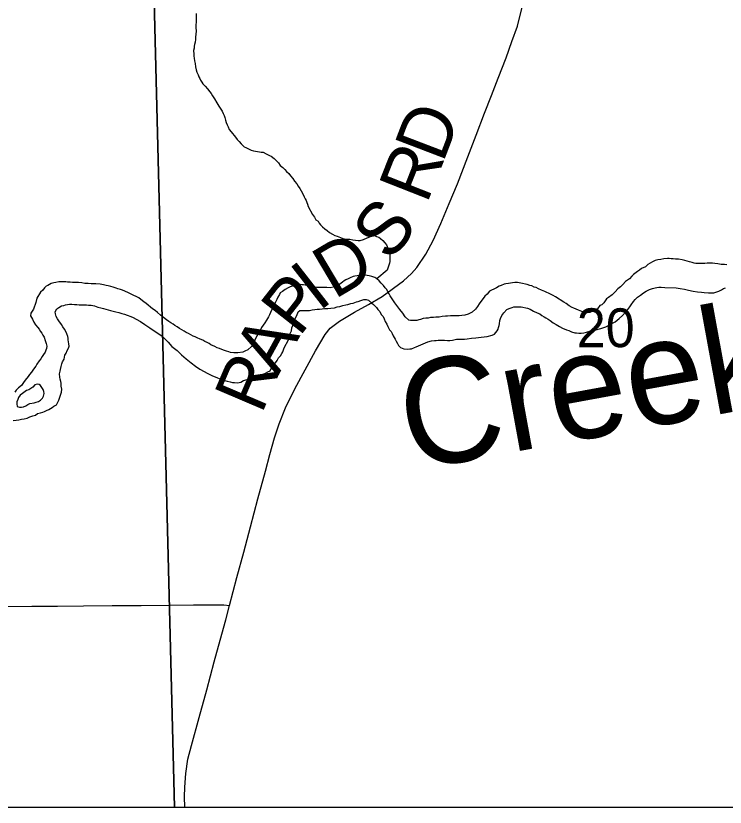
# Model space of a CAD drawing. Extents: x 103424 to 286016, y 38711 to 110967.
# Drawn here: x 153765 to 157824, y 38711 to 43242 of the extents above; entities that cross this region are included whole.
import ezdxf

# ---------------------------------------------------------------- set-up
doc = ezdxf.new("R2010")
doc.units = 0
for name, color, linetype in [('GM_X_Corporation', 7, 'Continuous'), ('GM_X_County_Road', 7, 'Continuous'), ('GM_X_County_Road_Text', 7, 'Continuous'), ('GM_X_Major_River', 7, 'Continuous'), ('GM_X_Major_River_Text', 7, 'Continuous'), ('GM_X_Minor_River', 7, 'Continuous'), ('GM_X_Section_Text', 7, 'Continuous'), ('GM_X_Township_Road', 7, 'Continuous')]:
    doc.layers.add(name, color=color, linetype=linetype)

msp = doc.modelspace()

# ---------------------------------------------------------------- linework, layer by layer
at = {"layer": 'GM_X_Corporation'}
for points in [[(103423.7, 96534.8), (103423.7, 38711.2), (175679.7, 38711.2), (175679.7, 110967.2), (119699, 110967.2), (119716.9, 106542.5), (119719.8, 106322.8), (119720.8, 106006.3), (119709.7, 99445.7), (119706.4, 99064.2), (119663.9, 96690), (117026.4, 96688.2), (115542.1, 96665), (105081.7, 96574.5)], [(149532.9, 38711.2), (174769.9, 38711.2), (174768.4, 38806.4), (174722.1, 40540.3), (174610.2, 44665.1), (172842.5, 44649), (172841.3, 44649), (167441.7, 44516.4), (162024.2, 44473.4), (156824.1, 44363.7), (149451.3, 44180.8), (149476.1, 42604.7), (149528, 39851)], [(154672.6, 38711.2), (159127.7, 38711.2), (159759.8, 38726.2), (159627, 44430), (159529.4, 44428), (157027.9, 44382), (154532, 44312.4)], [(149545.6, 38711.2), (154672.6, 38711.2), (154532, 44312.4), (154506.3, 44312.1), (151996.9, 44249.6), (149468.8, 44186.4), (149542.2, 39948.6)]]:
    msp.add_lwpolyline(points, close=True, dxfattribs=at)
at = {"layer": 'GM_X_County_Road'}
msp.add_lwpolyline([(154731.7, 38711.2), (154730.6, 38770), (154731.3, 38824.8), (154736.8, 38903.3), (154749.6, 38986.5), (154770.5, 39064.3), (154813.6, 39223.7), (154856.8, 39383), (154899.9, 39542.3), (154943.1, 39701.6), (154965.4, 39784.1), (154987.8, 39866.5), (155030, 40026.1), (155068.4, 40171.3), (155106.8, 40316.5), (155150, 40475.8), (155193.1, 40635.1), (155218.9, 40730.7), (155244.8, 40826.3), (155271.4, 40905.2), (155307.5, 40996.8), (155362.1, 41106.7), (155420.8, 41215.1), (155479.5, 41323.6), (155535.5, 41416.6), (155564.3, 41454.2), (155617.4, 41494), (155703, 41545.7), (155782, 41589.9), (155860.9, 41634.2), (155982.6, 41723.5), (156028.4, 41765.5), (156058.6, 41800.2), (156111.7, 41877), (156152.3, 41955.2), (156196.3, 42052.8), (156244, 42166.3), (156291.8, 42279.8), (156351, 42433.8), (156399.2, 42559.3), (156447.4, 42684.8), (156486.2, 42785.2), (156524.9, 42885.5), (156569.9, 43001.3), (156603.8, 43094.3), (156636.3, 43182.1), (156662.9, 43292.1)], dxfattribs=at)
at = {"layer": 'GM_X_Major_River'}
for points in [[(157834, 41815.3), (157819.8, 41817), (157801.6, 41818.6), (157791.4, 41820.4), (157781.3, 41822.2), (157765.1, 41823.9), (157750.9, 41825.6), (157734.7, 41825.2), (157720.6, 41824.9), (157706.5, 41824.6), (157696.4, 41824.4), (157686.3, 41824.2), (157668.1, 41823.8), (157656, 41823.5), (157645.8, 41825.3), (157635.6, 41829.1), (157619.4, 41832.8), (157607.2, 41836.6), (157592.9, 41840.3), (157576.7, 41844), (157556.4, 41847.6), (157540.2, 41849.3), (157526, 41851), (157513.9, 41850.7), (157503.8, 41852.5), (157493.7, 41852.3), (157473.5, 41849.9), (157455.4, 41847.4), (157439.2, 41845.1), (157423.2, 41840.7), (157407.2, 41832.3), (157395.2, 41825.9), (157381.2, 41817.6), (157367.3, 41805.1), (157345.3, 41794.6), (157333.4, 41786.2), (157321.4, 41777.9), (157299.6, 41761.3), (157289.7, 41751), (157275.8, 41736.5), (157263.9, 41728.2), (157254, 41719.9), (157238.1, 41703.4), (157224.2, 41691), (157210.4, 41678.6), (157194.6, 41662.1), (157176.8, 41643.5), (157156.9, 41629), (157144.9, 41620.6), (157129.2, 41598.1), (157117.3, 41587.7), (157107.3, 41583.5), (157093.5, 41565), (157079.5, 41558.6), (157065.6, 41550.3), (157049.5, 41543.9), (157033.4, 41541.5), (157023.3, 41541.3), (157002.9, 41548.9), (156984.6, 41556.6), (156970.3, 41562.3), (156958.1, 41568.1), (156947.9, 41571.9), (156931.5, 41581.7), (156913, 41595.4), (156900.7, 41603.2), (156853.6, 41632.5), (156839.3, 41640.2), (156825, 41648), (156812.7, 41653.8), (156802.6, 41657.6), (156792.3, 41663.4), (156782.1, 41667.2), (156772, 41671.1)], [(156772, 41671.1), (156755.6, 41678.8), (156741.3, 41686.5), (156731.2, 41688.3), (156716.9, 41696.1), (156706.7, 41697.9), (156690.4, 41703.6), (156680.3, 41705.4), (156664, 41709.1), (156653.9, 41710.9), (156635.6, 41714.5), (156619.4, 41714.2), (156607.3, 41713.9), (156595.2, 41711.6), (156583.2, 41709.4), (156569.1, 41707), (156559, 41704.8), (156541, 41698.3), (156531, 41694.1), (156515, 41683.6), (156499, 41677.2), (156487, 41670.9), (156475, 41664.6), (156461.2, 41648.1), (156449.3, 41635.8), (156439.5, 41623.4), (156425.7, 41607), (156415.9, 41592.6), (156406.1, 41578.3), (156394.3, 41561.9), (156376.5, 41545.4), (156364.5, 41539), (156352.5, 41532.7), (156334.4, 41528.3), (156316.3, 41525.9), (156302.2, 41523.6), (156286, 41523.2), (156267.8, 41524.8), (156251.6, 41524.5), (156235.5, 41522.1), (156223.4, 41521.8), (156205.2, 41519.4), (156187.1, 41517), (156168.9, 41516.6), (156154.8, 41514.3), (156136.6, 41513.9), (156124.6, 41511.6), (156110.4, 41511.3), (156096.3, 41509), (156080.3, 41502.6), (156070.2, 41500.3), (156060.2, 41498.1), (156042, 41497.7), (156023.8, 41497.3), (156013.7, 41499.1), (155993, 41518.8), (155978.5, 41538.7), (155961.8, 41560.6), (155945.2, 41582.4), (155932.7, 41598.3), (155907.6, 41638.1), (155901.3, 41650.1), (155893, 41662), (155886.7, 41674), (155878.4, 41683.9), (155868, 41697.8), (155855.5, 41711.7), (155843.2, 41723.5), (155830.8, 41735.4), (155818.5, 41743.2), (155802.2, 41748.9), (155785.9, 41752.6), (155775.8, 41754.4), (155763.6, 41756.1), (155753.5, 41755.9), (155739.4, 41755.6), (155729.3, 41755.4), (155717.2, 41753.1), (155705.1, 41750.8), (155695.1, 41748.6), (155677, 41742.1), (155667.1, 41735.8), (155653, 41729.5), (155643, 41725.2), (155633.1, 41716.9), (155611.2, 41700.3), (155595.2, 41691.9), (155581.2, 41687.6), (155563, 41685.1), (155544.8, 41686.7), (155526.6, 41686.4), (155510.5, 41686), (155496.3, 41685.7), (155486.2, 41685.5), (155476.1, 41687.3), (155437.5, 41696.5), (155421.2, 41700.2), (155411.1, 41702), (155401, 41701.8), (155390.8, 41703.6), (155374.7, 41701.2)], [(154040.4, 41718.6), (154020.2, 41718.2), (154010.1, 41717.9), (153994, 41715.6), (153982, 41713.3), (153965.9, 41708.9), (153947.9, 41698.4), (153937.9, 41694.2), (153928, 41683.9), (153918.2, 41671.5), (153906.3, 41659.1), (153884.8, 41624.4), (153879.3, 41600), (153865.9, 41561.4), (153850.3, 41538.8), (153848.5, 41524.6), (153859.1, 41504.7), (153867.5, 41488.7), (153877.9, 41472.8), (153890.4, 41456.9), (153898.7, 41447), (153905, 41435), (153913.3, 41425.1), (153919.6, 41413.1), (153925.9, 41401.1), (153932.4, 41383.1), (153938.8, 41365.1), (153941.2, 41351), (153939.5, 41336.8), (153935.6, 41326.7), (153931.8, 41316.5), (153922, 41302.1), (153916.2, 41291.9), (153908.4, 41277.6), (153898.5, 41267.3), (153884.8, 41246.8), (153878.9, 41236.6), (153865.2, 41218.1), (153853.4, 41201.7), (153843.6, 41187.4), (153835.7, 41177.1), (153818, 41156.5), (153808.2, 41142.2), (153796.4, 41125.8), (153780.6, 41111.3), (153766.7, 41098.9), (153758.9, 41086.6)], [(155374.7, 41701.2), (155358.6, 41698.9), (155346.6, 41694.6), (155334.5, 41690.3), (155322.6, 41683.9), (155306.6, 41675.5), (155290.7, 41663.1), (155276.7, 41656.7), (155272.8, 41646.5), (155263.1, 41630.1), (155257.3, 41617.9), (155251.5, 41605.7), (155247.6, 41595.5), (155243.8, 41585.3), (155236.1, 41569), (155226.3, 41552.6), (155222.5, 41542.5), (155216.7, 41530.2), (155210.9, 41518), (155199.2, 41499.5), (155189.4, 41483.2), (155179.6, 41470.9), (155169.8, 41456.5), (155158.1, 41432), (155150.3, 41419.7), (155144.5, 41409.5), (155134.8, 41389.1), (155125.1, 41372.8), (155119.3, 41358.5), (155113.4, 41348.3), (155091.6, 41329.6), (155075.6, 41321.2), (155063.6, 41316.9), (155035.4, 41312.3), (155023.3, 41312), (155011.2, 41311.7), (154992.9, 41313.3), (154982.7, 41317.2), (154970.5, 41320.9), (154958.3, 41324.7), (154944.1, 41330.5), (154929.8, 41336.2), (154917.6, 41340), (154903.3, 41347.7), (154880.8, 41357.3), (154870.6, 41365.2), (154860.3, 41371), (154846.1, 41376.8), (154833.8, 41384.6), (154819.5, 41390.3), (154803.2, 41398.1), (154790.9, 41403.8), (154778.7, 41407.6), (154766.4, 41415.4), (154752.1, 41423.2), (154739.9, 41429), (154727.6, 41436.8), (154715.3, 41444.6), (154701, 41452.4), (154688.7, 41460.2), (154674.3, 41467.9), (154664.1, 41475.8), (154651.8, 41483.6), (154639.5, 41491.4), (154627.2, 41501.2), (154608.7, 41515), (154592.2, 41528.7), (154575.7, 41542.5), (154561.3, 41554.3), (154547, 41564.1), (154509.9, 41595.6), (154497.7, 41603.4), (154479.2, 41617.1), (154468.8, 41627), (154452.5, 41634.7), (154440.3, 41640.5), (154428, 41646.3), (154409.6, 41656), (154389.2, 41665.6), (154374.9, 41671.4), (154362.7, 41675.1), (154348.5, 41678.9), (154338.3, 41682.7), (154322, 41688.4), (154307.8, 41692.1), (154293.6, 41695.8), (154281.4, 41697.6), (154267.2, 41701.3), (154246.9, 41704.9), (154222.6, 41706.4), (154196.3, 41707.9), (154178.1, 41709.5), (154159.9, 41709.1), (154141.6, 41712.7), (154123.4, 41714.4), (154105.2, 41714), (154089, 41715.6), (154074.8, 41717.3), (154060.7, 41717), (154050.5, 41718.8), (154040.4, 41718.6)], [(156286.8, 41390), (156309, 41390.5), (156321.2, 41390.7), (156331.3, 41390.9), (156347.4, 41393.3), (156371.6, 41395.9), (156397.8, 41398.4), (156428.1, 41401.1), (156462.3, 41405.9), (156490.5, 41412.6), (156504.5, 41418.9), (156518.2, 41437.4), (156524.1, 41447.6), (156525.9, 41457.8), (156529.7, 41467.9), (156531.5, 41478.1), (156535.1, 41498.3), (156538.9, 41508.5), (156546.6, 41526.8), (156556.4, 41541.2), (156574.2, 41559.8), (156588.2, 41566.1), (156604.3, 41572.5), (156614.3, 41574.8), (156632.5, 41575.2), (156644.6, 41575.4), (156656.8, 41575.7), (156693.3, 41568.4), (156707.6, 41562.7), (156726, 41550.9), (156748.4, 41541.3), (156762.7, 41535.6), (156775.1, 41525.8), (156787.3, 41518), (156797.6, 41512.1), (156809.9, 41504.3), (156822.2, 41496.5), (156838.6, 41484.7), (156857, 41475.1), (156875.4, 41463.3), (156893.8, 41453.6), (156916.2, 41444), (156928.5, 41440.3), (156944.8, 41432.5), (156963.1, 41426.9), (156973.2, 41427.1), (156985.4, 41425.4), (156999.5, 41425.7), (157015.7, 41426), (157029.7, 41430.4), (157049.8, 41436.9), (157084, 41443.7), (157112.1, 41452.3), (157140.2, 41461), (157166.2, 41473.7), (157194.2, 41490.5), (157218, 41509.1), (157235.9, 41525.7), (157253.7, 41544.2), (157267.4, 41560.7), (157277.3, 41575), (157285.1, 41587.3), (157298.8, 41605.8), (157308.7, 41618.1), (157322.6, 41630.6), (157338.5, 41643), (157356.4, 41655.5), (157372.3, 41665.9), (157390.3, 41674.4), (157408.4, 41680.9), (157422.4, 41685.2), (157432.5, 41685.4), (157444.6, 41687.7), (157456.7, 41688), (157479, 41686.4), (157543.7, 41683.8), (157566.1, 41680.3), (157590.4, 41676.7), (157614.7, 41671.2), (157641.1, 41665.7), (157665.5, 41662.2), (157687.8, 41658.7), (157704, 41657), (157728.3, 41655.5), (157744.4, 41655.9), (157758.6, 41656.2), (157770.6, 41660.5), (157786.7, 41664.9), (157802.7, 41673.3), (157814.7, 41679.6), (157824.7, 41683.9)], [(153862.8, 40951.6), (153876.8, 40955.9), (153888.8, 40964.3), (153904.9, 40968.6), (153918.9, 40973), (153928.9, 40977.2), (153941, 40981.5), (153953, 40987.9), (153972.9, 40998.4), (153982.9, 41006.7), (153996.8, 41015.1), (154010.4, 41041.6), (154018, 41064), (154025.6, 41086.4), (154027.3, 41104.6), (154024.9, 41120.7), (154024.5, 41138.8), (154022.3, 41148.9), (154018, 41160.9), (154015.7, 41172.9), (154015.3, 41191.1), (154019, 41207.3), (154020.8, 41217.5), (154024.5, 41233.7), (154028.2, 41249.9), (154032, 41260.1), (154041.8, 41276.5), (154045.4, 41298.8), (154053.2, 41311.1), (154058.9, 41325.3), (154066.7, 41339.6), (154070.5, 41349.8), (154068.2, 41363.9), (154065.9, 41375.9), (154063.7, 41386), (154063.5, 41396.1), (154061.3, 41406.1), (154056.9, 41420.2), (154050.5, 41434.1), (154042.2, 41448.1), (154033.8, 41462), (154025.5, 41474), (154010.8, 41495.9), (154002.5, 41507.8), (153996.2, 41519.8), (153991.8, 41535.8), (153989.5, 41547.9), (153999.3, 41564.3), (154011.2, 41572.6), (154025.2, 41581), (154039.3, 41583.3), (154049.3, 41587.6), (154059.4, 41589.8), (154071.5, 41590.1), (154085.6, 41590.4), (154099.8, 41588.7), (154114, 41589), (154126.1, 41587.2), (154138.2, 41587.5), (154154.4, 41587.8), (154168.6, 41586.1), (154180.7, 41584.4), (154194.9, 41584.7), (154205, 41582.9), (154215.2, 41581.1), (154233.5, 41573.4), (154251.8, 41569.8), (154266, 41566), (154280.3, 41562.3), (154292.4, 41558.5), (154306.7, 41554.8), (154320.9, 41551.1), (154337.2, 41547.4), (154353.4, 41543.7), (154371.7, 41538), (154385.9, 41534.3), (154402.2, 41528.6), (154422.6, 41521), (154436.9, 41515.2), (154453.2, 41505.5), (154477.8, 41491.9), (154502.4, 41474.3), (154531.1, 41454.7), (154596.7, 41411.7), (154615.3, 41394), (154635.9, 41374.2), (154656.7, 41348.4), (154687.5, 41324.9), (154712.3, 41301.2), (154739, 41277.5), (154767.8, 41255.9), (154792.5, 41236.3), (154817.1, 41218.7), (154841.6, 41205.1), (154860, 41195.4), (154874.4, 41187.6), (154886.6, 41181.8), (154898.8, 41176), (154915.1, 41170.3), (154931.5, 41162.6), (154953.9, 41155)], [(154953.9, 41155), (154974.2, 41149.4), (154990.4, 41145.7), (155004.7, 41142), (155016.8, 41142.3), (155033, 41140.6), (155043.1, 41142.8), (155053.1, 41145.1), (155067.1, 41153.4), (155101.2, 41164.3), (155125.3, 41170.9), (155141.4, 41175.3), (155151.4, 41179.5), (155161.5, 41181.8), (155179.5, 41190.2), (155193.5, 41196.6), (155207.5, 41203), (155219.5, 41209.3), (155227.2, 41225.6), (155239, 41244), (155250.9, 41254.4), (155260.7, 41268.7), (155268.4, 41283), (155278.3, 41295.3), (155286.1, 41307.6), (155292, 41317.8), (155299.6, 41340.2), (155324.8, 41387.2), (155330.6, 41403.5), (155334.2, 41423.7), (155341.9, 41438), (155343.6, 41456.3), (155349.4, 41468.5), (155356.9, 41494.9), (155364.6, 41513.2), (155372.4, 41525.5), (155380, 41547.9), (155390, 41554.2), (155410.2, 41554.6), (155428.4, 41555), (155444.5, 41555.4), (155460.7, 41557.7), (155474.8, 41560.1), (155488.9, 41562.4), (155503, 41562.7), (155517.1, 41565), (155531.2, 41565.3), (155549.4, 41565.7), (155567.6, 41568.1), (155587.7, 41570.6), (155603.8, 41575), (155617.9, 41577.3), (155635.9, 41583.8), (155652.1, 41586.1), (155664.1, 41588.4), (155682.2, 41594.9), (155694.3, 41597.1), (155714.3, 41603.6), (155724.4, 41605.9), (155738.4, 41612.2), (155756.5, 41616.7), (155768.6, 41616.9), (155782.8, 41613.2), (155801.4, 41597.5), (155811.6, 41589.6), (155828.2, 41571.8), (155836.5, 41559.9), (155846.9, 41548), (155855.3, 41532), (155865.7, 41520.1), (155872, 41506.1), (155878.4, 41492.1), (155886.8, 41476.2), (155893.2, 41462.2), (155903.7, 41444.2), (155912, 41434.3), (155918.3, 41422.3), (155924.6, 41410.4), (155935.1, 41390.4), (155941.5, 41378.4), (155947.8, 41366.4), (155954.1, 41354.5), (155966.5, 41342.6), (155984.8, 41334.9), (156003.1, 41333.3), (156019.2, 41335.7), (156029.3, 41335.9), (156045.3, 41342.3), (156055.3, 41346.6), (156069.3, 41352.9), (156121.4, 41374.3), (156143.5, 41380.8), (156159.6, 41383.2), (156169.7, 41383.4), (156181.8, 41385.7), (156198, 41384), (156218.2, 41384.4), (156234.4, 41382.8), (156248.6, 41383.1), (156262.7, 41385.4), (156286.8, 41390)], [(153906.2, 41126.1), (153898.4, 41131.1), (153886.3, 41133), (153874.2, 41128.8), (153862.3, 41116.5), (153838.3, 41100.1), (153826.3, 41095.9), (153802.3, 41079.4), (153790.3, 41069.2), (153780.4, 41057), (153776.5, 41044.8), (153770.6, 41032.6), (153770.7, 41020.5), (153773, 41004.4)], [(153773, 41004.4), (153785.1, 41000.5), (153797.2, 41000.7), (153809.3, 41002.9), (153821.3, 41009.1), (153833.3, 41017.3), (153845.3, 41021.5), (153869.5, 41025.9), (153881.5, 41030.1), (153893.5, 41034.3), (153905.6, 41040.5), (153917.5, 41052.7), (153923.4, 41064.9), (153927.3, 41079.1), (153925.1, 41091.2), (153920.9, 41103.2), (153906.2, 41126.1)], [(153750.2, 40924.9), (153766.3, 40927.3), (153782.4, 40929.6), (153796.5, 40932), (153812.6, 40934.3), (153828.7, 40938.7), (153844.7, 40945.1), (153862.8, 40951.6)]]:
    msp.add_lwpolyline(points, dxfattribs=at)
at = {"layer": 'GM_X_Minor_River'}
for points in [[(154795.9, 43255.3), (154797, 43204.8), (154795.2, 43190.7), (154795.6, 43174.5), (154796, 43154.3), (154794.4, 43136.1), (154792.7, 43119.9)], [(154792.7, 43119.9), (154793, 43105.8), (154791.3, 43091.7), (154787.5, 43077.4), (154785.7, 43067.3), (154786, 43057.2), (154782.2, 43043), (154782.6, 43022.8), (154782.9, 43010.7), (154785.2, 42998.7), (154787.5, 42984.6), (154789.9, 42968.5), (154792.3, 42950.4), (154796.7, 42932.3), (154801.1, 42918.2), (154807.4, 42904.2), (154811.7, 42892.2), (154818, 42882.3), (154822.2, 42872.3), (154828.5, 42862.3), (154834.8, 42852.4), (154847.2, 42838.5), (154861.7, 42822.7), (154874.2, 42806.8), (154882.5, 42796.9), (154890.8, 42782.9), (154901.3, 42767), (154913.9, 42743), (154926.4, 42725.1), (154936.9, 42707.2), (154945.3, 42695.3), (154951.6, 42683.3), (154955.9, 42671.3), (154960.2, 42659.2), (154964.5, 42645.2), (154968.9, 42631.2), (154973.2, 42617.1), (154979.5, 42605.2), (154985.9, 42591.2), (154996.3, 42577.3), (155021.2, 42547.5), (155031.6, 42533.6), (155041.9, 42521.7), (155054.4, 42507.9), (155070.9, 42492.1), (155081.1, 42488.3), (155095.4, 42480.5), (155111.7, 42472.8), (155123.9, 42469), (155136.1, 42467.2), (155148.2, 42465.5), (155158.4, 42463.7), (155168.5, 42461.9), (155180.7, 42460.1), (155197, 42452.4), (155215.4, 42442.7), (155225.6, 42438.9), (155242.1, 42425.1), (155258.6, 42409.4), (155266.9, 42399.4), (155277.3, 42385.5), (155291.7, 42373.7), (155304.1, 42361.9), (155314.4, 42350), (155326.8, 42338.2), (155337.1, 42326.3), (155349.6, 42310.4), (155360.1, 42294.5), (155372.5, 42280.6), (155380.9, 42266.7), (155389.2, 42252.7), (155397.6, 42238.8), (155408.2, 42218.8), (155414.5, 42204.8), (155420.8, 42194.8), (155425.1, 42184.8), (155429.4, 42172.8), (155433.6, 42162.8), (155437.9, 42150.8), (155463.1, 42104.9), (155473.6, 42089), (155482, 42073), (155494.3, 42065.2), (155500.6, 42055.3), (155508.9, 42045.3), (155519.2, 42033.4), (155533.6, 42021.7), (155546, 42011.8), (155560.3, 42002), (155576.7, 41992.3), (155591, 41984.5), (155603.2, 41980.8), (155621.6, 41973.1), (155635.8, 41967.3), (155654.1, 41963.7), (155676.4, 41962.2), (155692.6, 41958.5), (155708.8, 41956.8), (155723, 41955.1), (155735.1, 41955.4), (155753.2, 41961.8)], [(155753.2, 41961.8), (155775.2, 41970.4), (155799.3, 41981), (155813.3, 41985.3), (155827.6, 41977.6), (155841.9, 41973.8), (155852.1, 41966), (155864.5, 41956.2), (155876.9, 41942.3), (155885.2, 41930.4), (155889.5, 41920.4), (155895.9, 41902.3), (155900.2, 41892.3), (155902.4, 41882.3), (155904.7, 41870.2), (155905.4, 41835.9), (155903.6, 41825.8), (155890.3, 41785.1), (155830.8, 41735.4)]]:
    msp.add_lwpolyline(points, dxfattribs=at)
at = {"layer": 'GM_X_Township_Road'}
msp.add_lwpolyline([(153690.2, 39859.8), (153855.3, 39861), (154003.3, 39862.2), (154151.2, 39863.4), (154316.3, 39864.8), (154481.4, 39866.3), (154646.4, 39867.8), (154781.8, 39869), (154917.2, 39870.2), (154955.2, 39869.3), (154987.8, 39866.5)], dxfattribs=at)

# ---------------------------------------------------------------- texts
at = {"layer": 'GM_X_County_Road_Text'}
for s, rotation, p in [('D', 69.0742, (156207.9, 42393.7)), ('R', 68.5102, (156115.9, 42159.9)), ('S', 51.0698, (155903.6, 41827.4)), ('D', 30.6983, (155587, 41615.4)), ('I', 37.9393, (155497.6, 41544.9)), ('P', 51.8129, (155385.3, 41398.4)), ('A', 61.152, (155264.3, 41176.6)), ('R', 66.8931, (155170.5, 40955.7))]:
    msp.add_text(s, height=301.9, rotation=rotation, dxfattribs=at).set_placement(p)
at = {"layer": 'GM_X_Major_River_Text'}
msp.add_text('Creek', height=604.11, rotation=10.388, dxfattribs=at).set_placement((156020.4, 40635.4))
at = {"layer": 'GM_X_Section_Text'}
msp.add_text('20', height=222.38, rotation=0, dxfattribs=at).set_placement((156974.9, 41344.5))

doc.saveas('drawing.dxf')
